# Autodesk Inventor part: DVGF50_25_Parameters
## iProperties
Created: 2010-04
Part Number: DVGF50_25_Parameters
Document SubType Name: Modeling
Designer: TB
Density: 1 g/cm^3
Slaglengde: 100.000 mm
Vinkel_Plussport: 0.00 deg
Vinkel_Minusport: 0.00 deg
Forlengelse_rør: 0.000 mm
Author: TB
